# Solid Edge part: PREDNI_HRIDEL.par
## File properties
Author: knedlova
Template: Iso Metric Part.par
Last saved by: Acer
Revision: 29
Application: Solid Edge
Accuracy: 0,990
Username: Acer
Typ obsahu dokumentu: 0
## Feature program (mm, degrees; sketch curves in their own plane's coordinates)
sketch for "unnamed RevolvedProtrusion 1" plane through (0, 0, 0) normal (0, -1, 0) x-axis (1, 0, 0)
  line (62.3, 0) -> (62.3, 8)
  line (62.3, 8) -> (-89.7, 8)
  line (-89.7, 8) -> (-89.7, 0)
  dimension (linear) = 89.7
revolve "unnamed RevolvedProtrusion 1" add full turn 360 deg about sketch line (-89.7, 0) -> (62.3, 0)
sketch for "unnamed RevolvedCutout 1" plane through (0, 0, 0) normal (0, -1, 0) x-axis (1, 0, 0)
  line (62.3, 8) -> (0, 8)
  line (0, 8) -> (0, 6)
  line (0, 6) -> (62.3, 6)
  line (62.3, 6) -> (62.3, 8)
revolve "unnamed RevolvedCutout 1" cut finite 360 deg
sketch for "unnamed RevolvedCutout 2" plane through (0, 0, 0) normal (0, -1, 0) x-axis (1, 0, 0)
  line (62.3, 6) -> (22, 6)
  line (22, 6) -> (22, 5)
  line (22, 5) -> (62.3, 5)
  line (62.3, 5) -> (62.3, 6)
revolve "unnamed RevolvedCutout 2" cut finite 360 deg
sketch for "unnamed RevolvedCutout 3" plane through (0, 0, 0) normal (0, -1, 0) x-axis (1, 0, 0)
  line (62.3, 5) -> (45.5, 5)
  line (45.5, 5) -> (45.5, 4.8)
  line (45.5, 4.8) -> (62.3, 4.8)
  line (62.3, 4.8) -> (62.3, 5)
revolve "unnamed RevolvedCutout 3" cut full turn 360 deg
sketch for "unnamed RevolvedCutout 4" plane through (0, 0, 0) normal (0, -1, 0) x-axis (1, 0, 0)
  line (0, 0) -> (0, 0)
  line (-89.7, 8) -> (-36, 8)
  line (-36, 8) -> (-36, 6)
  line (-36, 6) -> (-89.7, 6)
  line (-89.7, 6) -> (-89.7, 8)
revolve "unnamed RevolvedCutout 4" cut full turn 360 deg
sketch for "unnamed RevolvedCutout 5" plane through (0, 0, 0) normal (0, -1, 0) x-axis (1, 0, 0)
  line (-89.7, 6) -> (-49, 6)
  line (-49, 6) -> (-49, 5)
  line (-49, 5) -> (-89.7, 5)
  line (-89.7, 5) -> (-89.7, 6)
revolve "unnamed RevolvedCutout 5" cut full turn 360 deg
sketch for "ExtrudedCutout_1" plane through (2, 0, 0) normal (1, 0, 0) x-axis (0, 1, 0)
  line (2, 5.6569) -> (2, 3.6)
  line (2, 3.6) -> (-2, 3.6)
  line (-2, 3.6) -> (-2, 5.6569)
extrude "ExtrudedCutout_1" cut finite 18 along +normal
fillet "Round_1" radius 2
fillet "Round_2" radius 0.4
slot "Slot_1"  SlotWidth = 4 mm
chamfer "Chamfer_1" setback 0.5  SetBackValue2 = 45 deg
sketch for "ExtrudedCutout_2" #1 plane through (62.3, 0, 0) normal (1, 0, 0) x-axis (0, 1, 0)
  line (-2.6533, 4) -> (2.6533, 4)
sketch for "ExtrudedCutout_2" #2 plane through (62.3, 0, 0) normal (1, 0, 0) x-axis (0, 1, 0)
  line (-2.6533, -4) -> (2.6533, -4)
  arc centre (0, 0) radius 4.8 from (-2.6533, -4) to (2.6533, -4) ccw
extrude "ExtrudedCutout_2" cut finite 16 along -normal
sketch for "Hole_1" plane through (62.3, 0, 0) normal (1, 0, 0) x-axis (0, 1, 0)
  line (0, 0) -> (0, 0)
  hole centre (0, 0) bore radius 1.621
hole "Hole_1" nominal diameter 4 finite  VBottomAngle = 118 deg; ThreadDepth = 8 mm
mirror "unnamed Mirror 1" of "Hole_1", "ExtrudedCutout_2", "Chamfer_1", "unnamed RevolvedCutout 3" about plane through (-13.7, 0, 0) normal (1, 0, 0)
revolve "unnamed RevolvedCutout 6" cut full turn 360 deg
chamfer "unnamed Chamfer 1"
extrude "unnamed Cutout 1" cut finite 16
hole "unnamed Hole 1" finite
chamfer "Chamfer_3" setback 0.2  SetBackValue2 = 45 deg
chamfer "Chamfer_4" setback 0.5  SetBackValue2 = 45 deg
sketch for "unnamed RevolvedCutout 7" plane through (0, 0, 0) normal (0, -1, 0) x-axis (1, 0, 0)
revolve "unnamed RevolvedCutout 7" cut full turn 360 deg
sketch for "unnamed RevolvedCutout 8" plane through (0, 0, 0) normal (0, -1, 0) x-axis (1, 0, 0)
revolve "unnamed RevolvedCutout 8" cut full turn 360 deg
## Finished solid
Body 1: solid body, 53 faces, 92 edges, 44 vertices.
  Faces by surface: plane 22, cylinder 19, cone 10, torus 2
  Edges by curve: circle 46, line 34, intersection 12
Bounding box of the edges (mm; curved faces can reach further): 152.000 x 16.000 x 16.000, from (-89.7, -8, -8) to (62.3, 8, 8).
Cylindrical faces by radius (mm): R0.4 x2, R1.621 x4, R2 x4, R4.8 x4, R5 x2, R6 x2, R8 x1
Conical faces (half-angle, radius in mm at the cone's reference point): 45 deg R4.3 x2, 45 deg R4.8 x3, 45 deg R5 x1, 45 deg R5.5 x1, 45 deg R6 x1, 59 deg R1.621 x2
Toroidal faces (ring radius, tube radius in mm): R1.6 r0.4 x2
Planar faces by outward normal: +x 6, +y 1, +z 4, -x 6, -y 2, -z 3
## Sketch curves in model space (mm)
line (-46, -6, 0) -> (-40, -6, 0)
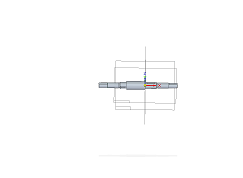
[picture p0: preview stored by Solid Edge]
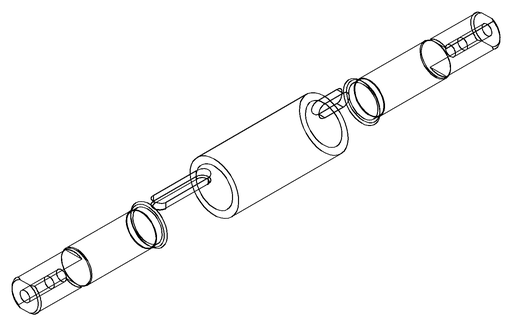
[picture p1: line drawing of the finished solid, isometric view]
